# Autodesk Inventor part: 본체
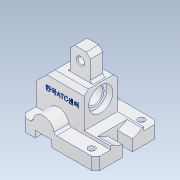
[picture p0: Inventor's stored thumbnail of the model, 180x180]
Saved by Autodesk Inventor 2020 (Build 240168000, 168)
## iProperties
Created: 2022-08
Part Number: 본체
Material: 알루미늄 6061
Document SubType Name: Modeling
Designer: user
Density: 2.7 g/cm^3
Appearance: 알루미늄 - 평지
Mass: 499.034 g
Surface Area: 338.04 cm^2
Volume: 184.828 cm^3
Author: user
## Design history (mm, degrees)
sketch "스케치1"
  geometry: L1 (32, -27)-(-58, -27); L2 (-58, -27)-(-58, -42); L3 (-58, -42)-(32, -42); L4 (32, -42)-(32, -27); L5 (32, -27)-(-58, -42); L6 (-58, -27)-(32, -42); C1 r 13 at (-31, -27); 4 further points
  constraints: 12 end point, 2 midpoint, 2 parallel, 1 centre point, 1 horizontal, 1 perpendicular, 1 point on line
  dimensions: "d0" = 15 distance of L1.end L2.end; "d1" = 90 distance of L2.end L3.end; "d2" = 26 diameter of C1; "d3" = 27 distance from line of C1.centre L2; "d4" = 42 distance from line of L3 point (0, 0); "d5" = 32 distance from line of L4 point (0, 0)
extrude "돌출1" new body sketch "스케치1" stored distance "d6" = 76; taper "d7" = 0 deg
sketch "스케치2"
  geometry: L1 (0, 18)-(-58, 18); L2 (-58, 18)-(-58, -27); L3 (-58, -27)-(0, -27); L4 (0, -27)-(0, 18); L5 (0, 18)-(-58, -27); L6 (-58, 18)-(0, -27); 3 further points
  constraints: 12 end point, 2 midpoint, 2 parallel, 1 coincident, 1 horizontal, 1 perpendicular, 1 vertical alignment
  dimensions: "d8" = 45 distance of L1.end L2.end
extrude "돌출2" join sketch "스케치2" stored distance "d9" = 40; taper "d10" = 0 deg
chamfer "모따기1" distance "d11" = 18; stored, may be unused: second distance "d12" = 2, angle "d13" = 45 deg
sketch "스케치3"
  geometry: C1 r 14.5 at (20, 27); 1 further point
  constraints: 1 centre point, 1 coincident
  dimensions: "d14" = 29 diameter of C1
extrude "돌출3" cut sketch "스케치3" distance "d15" = 7; taper "d16" = 0 deg
sketch "스케치4"
  geometry: C1 r 10 at (0, 0); 1 further point
  constraints: 1 centre point, 1 coincident
  dimensions: "d17" = 20 diameter of C1
extrude "돌출4" cut sketch "스케치4" extent not by distance; stored distance "d18" = 0; taper "d19" = 0 deg
sketch "스케치5"
  geometry: L1 (-5, 27.5)-(-29, 27.5); L2 (-29, 27.5)-(-29, 12.5); L3 (-29, 12.5)-(-5, 12.5); L4 (-5, 12.5)-(-5, 27.5); L5 (-5, 27.5)-(-29, 12.5); L6 (-29, 27.5)-(-5, 12.5); L7 (0, 40)-(0, 0) reference; 4 further points
  constraints: 12 end point, 4 midpoint, 2 parallel, 1 horizontal, 1 horizontal alignment, 1 perpendicular
  dimensions: "d20" = 5 distance between parallel lines of L7 L4; "d21" = 24 distance of L1.start L1.end; "d22" = 15 distance of L1.end L2.end
extrude "돌출5" join sketch "스케치5" distance "d23" = 30; taper "d24" = 0 deg
chamfer "모따기2" distance "d25" = 5; stored, may be unused: second distance "d26" = 2, angle "d27" = 45 deg
sketch "스케치6"
  geometry: L1 (24, 0)-(24, 25) reference; C1 r 4 at (12, 17); 1 further point
  constraints: 1 centre point
  dimensions: "d28" = 8 diameter of C1; "d29" = 35 vertical distance of C1.centre point (29, -18); "d30" = 12 distance from line of L1 C1.centre
extrude "돌출6" cut sketch "스케치6" extent not by distance; stored distance "d31" = 0; taper "d32" = 0 deg
chamfer "모따기3" distance "d33" = 1; stored, may be unused: second distance "d34" = 2, angle "d35" = 45 deg
sketch "스케치7"
  geometry: L1 (76, 15)-(0, 15) reference; L2 (58, 19)-(18, 19); L3 (18, 19)-(18, 15); L4 (18, 15)-(58, 15); L5 (58, 15)-(58, 19); L6 (58, 19)-(18, 15); L7 (18, 19)-(58, 15); L8 (18, 15)-(18, 60) reference; L9 (58, 60)-(58, 15) reference; L10 (58, 60)-(18, 60) reference; L11 (76, 0)-(0, 0) reference; 4 further points
  constraints: 12 end point, 2 midpoint, 2 parallel, 2 point on line, 1 horizontal, 1 perpendicular
  dimensions: "d36" = 45 distance between parallel lines of L4 L10; "d37" = 19 distance between parallel lines of L2 L11
extrude "돌출7" join sketch "스케치7" distance "d38" = 32; taper "d39" = 0 deg
sketch "스케치8"
  geometry: C1 r 29 at (38, 42); 1 further point
  constraints: 1 centre point, 1 coincident
  dimensions: "d40" = 58 diameter of C1
extrude "돌출8" cut sketch "스케치8" distance "d41" = 18; taper "d42" = 0 deg
sketch "스케치9"
  geometry: L1 (44, 19)-(32, 19); L2 (32, 19)-(32, 0); L3 (32, 0)-(44, 0); L4 (44, 0)-(44, 19); L5 (44, 19)-(32, 0); L6 (32, 19)-(44, 0); L7 (76, 0)-(0, 0) reference; L8 (20.336, 19)-(55.664, 19) reference; 3 further points
  constraints: 12 end point, 3 midpoint, 2 parallel, 2 point on line, 1 horizontal, 1 perpendicular, 1 vertical alignment
  dimensions: "d43" = 12 distance of L2.end L3.end
extrude "돌출9" cut sketch "스케치9" distance "d44" = 18; taper "d45" = 0 deg
sketch "스케치10"
  geometry: L1 (50, 76)-(50, 58) reference; 3 further points
  constraints: 1 vertical alignment
  dimensions: "d46" = 13 distance from line of L1 point (37, 68); "d47" = 30 vertical distance of point (37, 68) point (18, 38); "d48" = 60 distance of point (37, 8) point (37, 68)
hole "구멍1" sketch "스케치10" at (37, 68), (37, 8) diameter "d49" = 4.5; stored, may be unused: countersink angle "d53" = 90 deg, drill point angle "d55" = 118 deg; dims "d50" = 6, "d51" = 8, "d52" = 4.4, "d54" = 8
chamfer "모따기4" distance "d56" = 5; stored, may be unused: second distance "d57" = 2, angle "d58" = 45 deg
sketch "스케치11"
  geometry: L1 (-21, -34)-(-41, -34); L2 (-41, -34)-(-41, -42); L3 (-41, -42)-(-21, -42); L4 (-21, -42)-(-21, -34); L5 (-21, -34)-(-41, -42); L6 (-41, -34)-(-21, -42); L7 (-58, -27)-(-58, -42) reference; L8 (-53, -42)-(27, -42) reference; 2 further points
  constraints: 12 end point, 2 midpoint, 2 parallel, 1 horizontal, 1 perpendicular, 1 point on line
  dimensions: "d59" = 27 distance from line of point (-31, -38) L7; "d60" = 20 distance of L1.start L1.end; "d61" = 8 distance of L1.end L2.end
extrude "돌출10" cut sketch "스케치11" extent not by distance; stored distance "d62" = 0; taper "d63" = 0 deg
chamfer "모따기5" distance "d64" = 5; stored, may be unused: second distance "d65" = 2, angle "d66" = 45 deg
fillet "모깎기1" dims "d67" = 3
fillet "모깎기2" dims "d68" = 3
node "작업 평면1"
sketch "스케치12"
  geometry: L1 (0, -23)-(0, 13) reference; L2 (0, 18)-(-40, 18) reference; 2 further points
  constraints: 1 other
  dimensions: "d70" = 26 distance from line of L1 point (-26, 0); "d71" = 18 distance from line of L2 point (-26, 0)
feature "엠보싱1" sketch "스케치12" dims "d0" = 15, "d1" = 90, "d2" = 26, "d3" = 27, "d4" = 42, "d5" = 32, "d72" = 0.5, "d73" = 0
node "솔리드1"
other parameters: "d69" = 96
